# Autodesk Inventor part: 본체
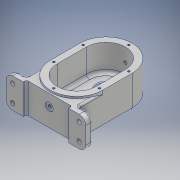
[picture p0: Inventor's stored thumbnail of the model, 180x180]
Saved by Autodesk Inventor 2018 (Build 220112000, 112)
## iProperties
Created: 2021-05
Part Number: 본체
Material: 알루미늄 6061
Document SubType Name: Modeling
Designer: Admin
Mass: 756.755 g
Surface Area: 581.829 cm^2
Volume: 280.28 cm^3
Density: 2.7 g/cm^3
Appearance: 알루미늄 - 평지
Author: Admin
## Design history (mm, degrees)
sketch "스케치1"
  geometry: L1 (0, 0)-(0, -45); L2 (-40, 0)-(-40, -45); L3 (40, -45)-(40, 0); L4 (-56, 0)-(56, 0) reference; L5 (0, -110)-(0, 65) reference; A1 r 40 centre (0, 0) between (40, 0) and (-40, 0); A2 r 40 centre (0, -45) between (-40, -45) and (40, -45); 1 further point
  constraints: 8 end point, 4 point on circle, 4 tangent, 2 centre point, 2 midpoint, 1 parallel, 1 vertical
  dimensions: "d0" = 80 distance between parallel lines of L3 L2; "d1" = 45 distance of L3.start L3.end
extrude "돌출1" new body sketch "스케치1" distance "d2" = 21; taper "d4" = 0 deg; dims "d3" = 28, "d5" = 0
node "작업 평면1"
sketch "스케치2"
  geometry: L1 (61, 18)-(-61, 18); L2 (-61, 18)-(-61, -28); L3 (-61, -28)-(61, -28); L4 (61, -28)-(61, 18); L5 (61, 18)-(-61, -28); L6 (-61, 18)-(61, -28); L7 (40, 21)-(-40, 21) reference; L8 (0, -37.8)-(0, 30.8) reference; 2 further points
  constraints: 12 end point, 3 midpoint, 2 parallel, 1 horizontal, 1 perpendicular, 1 point on line
  dimensions: "d7" = 122 distance of L2.end L3.end; "d8" = 46 distance of L1.end L2.end; "d9" = 3 distance between parallel lines of L7 L1
extrude "돌출2" join sketch "스케치2" distance "d10" = 10; taper "d11" = 0 deg
sketch "스케치3"
  geometry: L1 (-24.4, 92)-(146.4, 92) reference; L2 (61, -26.4)-(61, 158.4) reference; L3 (21, 47)-(21, 92) reference; L4 (122, 10)-(76.199, 10) reference; L5 (21, 92)-(101, 92); L6 (101, 92)-(101, 10); L7 (101, 10)-(21, 10); L8 (21, 10)-(21, 92); 2 further points
  constraints: 8 end point, 2 parallel, 1 horizontal, 1 perpendicular, 1 point on line, 1 vertical alignment
extrude "돌출3" join sketch "스케치3" stored distance "d12" = 10; taper "d13" = 0 deg
sketch "스케치4"
  geometry: L1 (-56, 0)-(56, 0) reference; L2 (0, -110)-(0, 65) reference; L3 (0, 0)-(0, -45); L4 (-30, 0)-(-30, -45); L5 (30, -45)-(30, 0); A1 r 40 centre (0, 0) between (40, 0) and (-40, 0) reference; A2 r 40 centre (0, -45) between (-40, -45) and (40, -45) reference; A3 r 30 centre (0, 0) between (30, 0) and (-30, 0); A4 r 30 centre (0, -45) between (-30, -45) and (30, -45); 2 further points
  constraints: 8 end point, 4 point on circle, 4 tangent, 2 centre point, 1 collinear, 1 midpoint, 1 parallel
  dimensions: "d14" = 60 distance between parallel lines of L4 L5
extrude "돌출4" cut sketch "스케치4" distance "d15" = 41; taper "d16" = 0 deg
sketch "스케치5"
  geometry: L1 (85.4, 0)-(-85.4, 0) reference; L2 (0, -118.4)-(0, 66.4) reference; L3 (-26, 0)-(-26, -30); L4 (26, -30)-(26, 0); L5 (-26, -30)-(26, -30); A1 r 26 centre (0, 0) between (26, 0) and (-26, 0)
  constraints: 6 end point, 2 point on circle, 2 tangent, 1 centre point, 1 parallel, 1 perpendicular, 1 other
  dimensions: "d17" = 52 distance between parallel lines of L4 L3; "d18" = 30 distance of L3.start L3.end
extrude "돌출5" join sketch "스케치5" distance "d19" = 8; taper "d20" = 0 deg
sketch "스케치6"
  geometry: L1 (85.4, 0)-(-85.4, 0) reference; L2 (0, -118.4)-(0, 66.4) reference; L3 (0, -45)-(0, -7.555); L4 (-26, -45)-(-26, -30); L5 (26, -30)-(26, -45); L6 (-26, -30)-(26, -30) reference; L7 (-26, -30)-(-26, 0) reference; L8 (-26, -30)-(26, -30); L9 (-61, -92)-(61, -92) reference; A1 r 26 centre (0, -45) between (-26, -45) and (26, -45)
  constraints: 10 end point, 4 point on line, 2 equal length, 2 point on circle, 2 tangent, 1 centre point, 1 perpendicular
  dimensions: "d21" = 52 distance between parallel lines of L5 L4; "d22" = 47 distance from line of L9 L4.start
extrude "돌출6" join sketch "스케치6" distance "d23" = 11; taper "d24" = 0 deg
sketch "스케치7"
  geometry: L1 (0, -20)-(30, -20) reference; L2 (14, -20)-(0, -20); L3 (0, -28)-(13.7, -28); L4 (14, -27.7)-(14, -20); L5 (11, -28)-(11, -32); L6 (11, -32)-(14, -32); L7 (14, -32)-(14, -36); L8 (0, -36)-(26, -36) reference; L9 (0, -51)-(0, 33) reference; L10 (0, -28)-(0, -36) reference; L11 (0, -20)-(0, -36); A1 r 0.3 centre (13.7, -27.7) between (13.7, -28) and (14, -27.7); 1 further point
  constraints: 14 end point, 5 point on line, 2 perpendicular, 2 point on circle, 2 tangent, 1 centre point, 1 collinear, 1 horizontal, 1 parallel, 1 vertical
  dimensions: "d27" = 22 diameter of L5 L9; "d28" = 4 distance of L6.end L7.end; "d29" = 28 diameter of L7 L9; "d30" = 28 diameter of L4 L9; "d31" = 0.3 radius of A1 (derived)
revolve "회전1" sketch "스케치7" stored, may be unused: angle "d32" = 90 deg
sketch "스케치8"
  geometry: L1 (-45, -20)-(0, -20) reference; L2 (-31, -20)-(-45, -20); L3 (-45, -20)-(-45, -28); L4 (-45, -28)-(-31.3, -28); L5 (-31, -27.7)-(-31, -20); L6 (-35, -28)-(-45, -28); L7 (-45, -28)-(-45, -32); L8 (-45, -32)-(-38, -32); L9 (-35, -29)-(-35, -28); L10 (-45, 21)-(-45, -20) reference; A1 r 0.3 centre (-31.3, -27.7) between (-31.3, -28) and (-31, -27.7); A2 r 3 centre (-38, -29) between (-38, -32) and (-35, -29); 3 further points
  constraints: 16 end point, 8 point on line, 4 parallel, 4 point on circle, 4 tangent, 2 centre point, 2 horizontal, 2 perpendicular
  dimensions: "d33" = 28 diameter of L5 L10; "d34" = 10 distance between parallel lines of L7 L9; "d35" = 8 distance of point (-31, -28) L2.start; "d36" = 4 distance of point (-35, -32) L6.start; "d37" = 0.3 radius of A1 (derived); "d38" = 3 radius of A2
revolve "회전2" sketch "스케치8" stored, may be unused: angle "d39" = 90 deg
sketch "스케치12"
  geometry: L1 (-24.4, 92)-(146.4, 92) reference; L2 (61, -27)-(61, 162) reference; L3 (26, -5)-(96, -5); L4 (96, -5)-(96, 2); L5 (93, 5)-(29, 5); L6 (26, 2)-(26, -5); L7 (122, 0)-(0, 0) reference; L8 (26, -5)-(96, 5); L9 (96, -5)-(26, 5); A1 r 3 centre (93, 2) between (96, 2) and (93, 5); A2 r 3 centre (29, 2) between (29, 5) and (26, 2); 2 further points
  constraints: 12 end point, 4 point on circle, 4 point on line, 4 tangent, 3 midpoint, 2 centre point, 2 parallel, 1 horizontal, 1 perpendicular
  dimensions: "d60" = 70 distance of L3.start L3.end; "d61" = 5 distance between parallel lines of L5 L7; "d62" = 3 radius of A1 (derived); "d63" = 3 radius of A2 (derived)
extrude "돌출8" cut sketch "스케치12" extent not by distance; stored distance "d64" = 11; taper "d65" = 0 deg
fillet "모깎기1" dims "d40" = 5
sketch "스케치9"
  geometry: L1 (0, 0)-(0, -45); L2 (-35, 0)-(-35, -45); L3 (35, -45)-(35, 0); L4 (-85.4, 0)-(85.4, 0) reference; L5 (0, -118.4)-(0, 66.4) reference; A1 r 30 centre (0, -45) between (-30, -45) and (30, -45) reference; A2 r 35 centre (0, 0) between (35, 0) and (-35, 0); A3 r 35 centre (0, -45) between (-35, -45) and (35, -45); 7 further points
  constraints: 8 end point, 6 point on circle, 4 coincident, 4 tangent, 2 centre point, 2 point on line, 1 midpoint, 1 parallel, 1 vertical
  dimensions: "d41" = 70 distance between parallel lines of L3 L2
hole "구멍1" sketch "스케치9" at (0, 35), (-35, 0), (-35, -45), (0, -80), (35, -45), (35, 0) diameter "d42" = 3.242; stored, may be unused: countersink angle "d46" = 90 deg, drill point angle "d48" = 118 deg; dims "d43" = 8, "d44" = 4, "d45" = 2, "d47" = 10
node "작업 평면2"
sketch "스케치10"
  geometry: C1 r 6 at (0, 0); 1 further point
  constraints: 1 centre point, 1 coincident
  dimensions: "d50" = 12 diameter of C1
extrude "돌출7" join sketch "스케치10" stored distance "d51" = 11; taper "d52" = 0 deg; dims "d7" = 122, "d8" = 46, "d9" = 3
sketch "스케치13"
  geometry: C1 r 6 at (32, -18) reference; 2 further points
  constraints: 1 coincident
hole "구멍3" sketch "스케치13" at (32, -18) diameter "d66" = 4.917; stored, may be unused: countersink angle "d70" = 90 deg, drill point angle "d72" = 118 deg; dims "d67" = 140, "d68" = 12, "d69" = 1, "d71" = 17.1
sketch "스케치14" dims "d73" = 40
  geometry: L1 (85.4, 0)-(-85.4, 0) reference; L2 (0, -119)-(0, 70) reference; 3 further points
  constraints: 1 coincident, 1 point on line, 1 vertical alignment, 2 other
hole "구멍4" sketch "스케치14" at (0, 20) diameter "d74" = 3.242; stored, may be unused: countersink angle "d78" = 90 deg, drill point angle "d80" = 118 deg; dims "d75" = 8, "d76" = 12, "d77" = 1, "d79" = 10
fillet "모깎기2" dims "d84" = 10
sketch "스케치15"
  geometry: A1 r 10 centre (-51, 18) between (-51, 28) and (-61, 18) reference; A2 r 10 centre (-51, -8) between (-61, -8) and (-51, -18) reference; A3 r 10 centre (51, 18) between (61, 18) and (51, 28) reference; A4 r 10 centre (51, -8) between (51, -18) and (61, -8) reference; 5 further points
  constraints: 4 coincident
hole "구멍5" sketch "스케치15" at (-51, 18), (-51, -8), (51, 18), (51, -8) diameter "d85" = 6.6; stored, may be unused: countersink angle "d89" = 90 deg, drill point angle "d91" = 118 deg; dims "d86" = 8, "d87" = 11, "d88" = 2, "d90" = 10
chamfer "모따기1" distance "d92" = 1; stored, may be unused: second distance "d93" = 2, angle "d94" = 45 deg
fillet "모깎기3" dims "d95" = 3
sketch "스케치16"
  geometry: L1 (0, -119.006)-(0, 70.034) reference; L2 (-51, -92)-(-35, -92) reference; 2 further points
  constraints: 1 point on line, 1 other
  dimensions: "d96" = 12 distance from line of L2 point (0, -80)
feature "엠보싱1" sketch "스케치16" dims "d0" = 80, "d1" = 45, "d97" = 0.5, "d98" = 0
node "솔리드1"
pattern_circular "원형 패턴1" dims angle "d82" = 360 deg
other parameters: "d6" = -92, "d49" = -135
